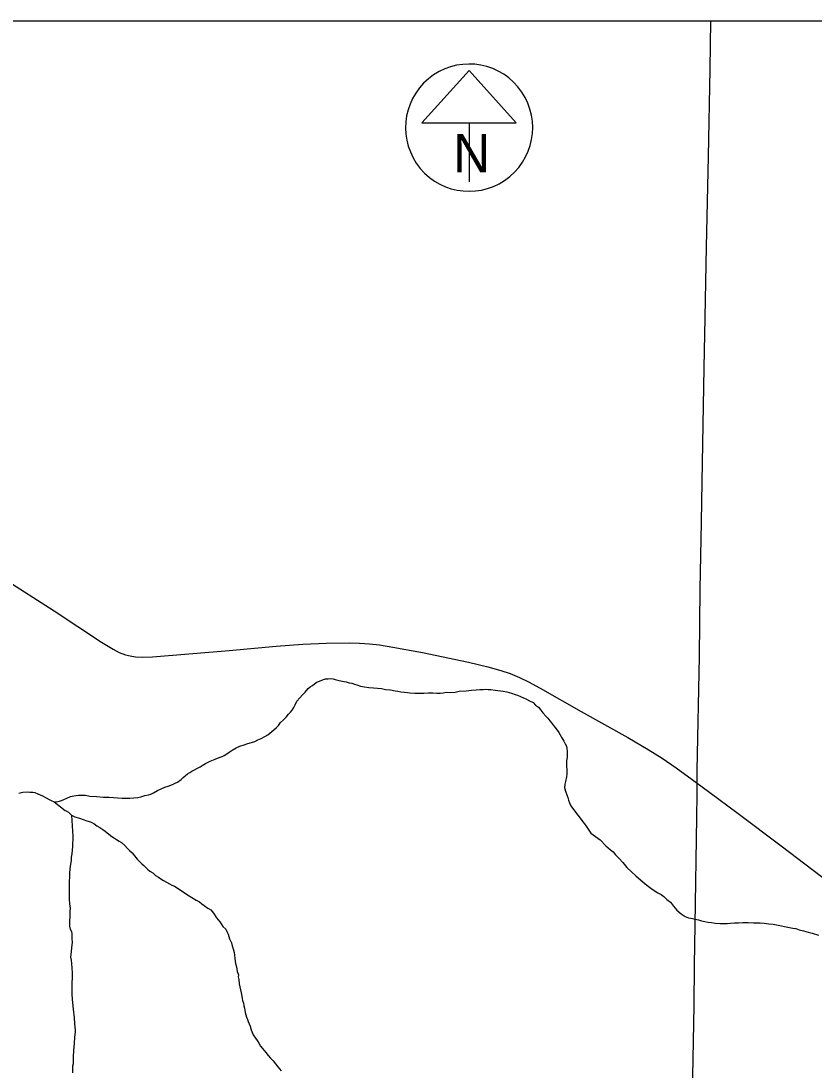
# Model space of a CAD drawing. Extents: x 1 to 1675, y -2 to 1113.
# Drawn here: x 1661.53 to 1666.71, y 1098.56 to 1105.4 of the extents above; entities that cross this region are included whole.
import ezdxf

# ---------------------------------------------------------------- set-up
doc = ezdxf.new("R2010")
doc.units = 0
for name, color, linetype in [('SC_Scratch1', 7, 'Continuous'), ('SH_Data', 7, 'Continuous'), ('SN_P_Text', 7, 'Continuous')]:
    doc.layers.add(name, color=color, linetype=linetype)

msp = doc.modelspace()

# ---------------------------------------------------------------- linework, layer by layer
at = {"layer": 'SC_Scratch1'}
for points in [[(1661.7617, 1100.3085), (1661.7832, 1100.3135), (1661.7967, 1100.3161), (1661.8129, 1100.3239), (1661.8318, 1100.3317), (1661.8561, 1100.3421), (1661.8776, 1100.3471), (1661.9072, 1100.3521), (1661.9341, 1100.3518), (1661.9529, 1100.3515), (1661.9823, 1100.3458), (1662.0253, 1100.3425), (1662.0709, 1100.3392), (1662.1058, 1100.3388), (1662.1353, 1100.3357), (1662.1648, 1100.3353), (1662.1916, 1100.3323), (1662.2185, 1100.332), (1662.2427, 1100.3316), (1662.2669, 1100.334), (1662.2937, 1100.3363), (1662.3153, 1100.3414), (1662.3396, 1100.3491), (1662.3638, 1100.3542), (1662.38, 1100.3593), (1662.3962, 1100.3671), (1662.4232, 1100.3828), (1662.4475, 1100.3932), (1662.4719, 1100.4036), (1662.4934, 1100.4114), (1662.5204, 1100.4217), (1662.5393, 1100.4295), (1662.5528, 1100.4374), (1662.5772, 1100.4531), (1662.5908, 1100.4664), (1662.6044, 1100.4769), (1662.6179, 1100.4901), (1662.6342, 1100.5006), (1662.6477, 1100.5085), (1662.7018, 1100.5372), (1662.7153, 1100.5451), (1662.737, 1100.5582), (1662.7667, 1100.5739), (1662.7991, 1100.5869), (1662.8261, 1100.5972), (1662.845, 1100.605), (1662.8585, 1100.6102), (1662.8747, 1100.6207), (1662.891, 1100.6312), (1662.9099, 1100.6443), (1662.937, 1100.6601), (1662.9613, 1100.6704), (1662.9883, 1100.6808), (1663.0125, 1100.6885), (1663.0368, 1100.6962), (1663.0584, 1100.7013), (1663.0773, 1100.7118), (1663.0989, 1100.7222), (1663.1232, 1100.7353), (1663.1422, 1100.7458), (1663.1557, 1100.7563), (1663.1829, 1100.7774), (1663.1992, 1100.7932), (1663.2128, 1100.8064), (1663.2264, 1100.825), (1663.2455, 1100.8435), (1663.2618, 1100.8594), (1663.2781, 1100.8806), (1663.2917, 1100.8938), (1663.3026, 1100.9071), (1663.3136, 1100.923), (1663.3219, 1100.9416), (1663.3329, 1100.9656), (1663.352, 1100.9868), (1663.3683, 1101.0053), (1663.3874, 1101.0238), (1663.4065, 1101.0477), (1663.42, 1101.0582), (1663.4336, 1101.0661), (1663.458, 1101.0872), (1663.5066, 1101.1053), (1663.5201, 1101.1105), (1663.5362, 1101.1103), (1663.5523, 1101.1127), (1663.5684, 1101.1098), (1663.5818, 1101.107), (1663.6005, 1101.1014), (1663.6273, 1101.0957), (1663.6541, 1101.0899), (1663.6728, 1101.0843), (1663.6916, 1101.0814), (1663.7076, 1101.0759), (1663.7237, 1101.0703), (1663.7477, 1101.0619), (1663.7745, 1101.0589), (1663.8013, 1101.0532), (1663.8335, 1101.0528), (1663.8577, 1101.0498), (1663.8845, 1101.0468), (1663.9113, 1101.041), (1663.9435, 1101.0379)], [(1663.9435, 1101.0379), (1663.9729, 1101.0322), (1663.9917, 1101.0293), (1664.0105, 1101.0263), (1664.0346, 1101.0233), (1664.0533, 1101.0204), (1664.0695, 1101.0202), (1664.1017, 1101.0171), (1664.1339, 1101.0167), (1664.1607, 1101.0163), (1664.1903, 1101.0186), (1664.2198, 1101.0182), (1664.2467, 1101.0179), (1664.2682, 1101.0176), (1664.287, 1101.0201), (1664.3058, 1101.0225), (1664.3354, 1101.0221), (1664.3649, 1101.0244), (1664.3918, 1101.0294), (1664.4375, 1101.0315), (1664.4725, 1101.0364), (1664.5021, 1101.0387), (1664.5263, 1101.041), (1664.5477, 1101.0407), (1664.5639, 1101.0432), (1664.58, 1101.0403), (1664.5988, 1101.0401), (1664.6256, 1101.037), (1664.6792, 1101.031), (1664.7033, 1101.0253), (1664.7328, 1101.0169), (1664.7568, 1101.0085), (1664.7729, 1101.003), (1664.7916, 1100.9947), (1664.8103, 1100.9864), (1664.8316, 1100.9781), (1664.8503, 1100.9671), (1664.8743, 1100.9561), (1664.8902, 1100.9398), (1664.9089, 1100.9262), (1664.9247, 1100.9072), (1664.9379, 1100.8883), (1664.9565, 1100.8666), (1664.9697, 1100.853), (1664.9829, 1100.8368), (1664.9935, 1100.8233), (1665.0067, 1100.807), (1665.0253, 1100.7854), (1665.0411, 1100.761), (1665.0621, 1100.7259), (1665.0753, 1100.7043), (1665.0831, 1100.6855), (1665.091, 1100.672), (1665.0935, 1100.6559), (1665.0959, 1100.6398), (1665.0957, 1100.6237), (1665.0955, 1100.6023), (1665.0924, 1100.5729), (1665.092, 1100.5407), (1665.0944, 1100.5166), (1665.0941, 1100.4898), (1665.0911, 1100.4711), (1665.0854, 1100.4417), (1665.0798, 1100.423), (1665.0795, 1100.3989), (1665.0872, 1100.372), (1665.095, 1100.3532), (1665.1002, 1100.337), (1665.1053, 1100.3182), (1665.1105, 1100.3021), (1665.121, 1100.2832), (1665.1579, 1100.2318), (1665.1738, 1100.2102), (1665.1923, 1100.1858), (1665.2161, 1100.156), (1665.2503, 1100.1047), (1665.3115, 1100.061), (1665.3486, 1100.0204), (1665.3779, 1099.9959), (1665.3965, 1099.9822), (1665.4124, 1099.9633), (1665.4362, 1099.9389), (1665.4601, 1099.9118), (1665.4865, 1099.8793), (1665.5157, 1099.8521), (1665.5449, 1099.8249), (1665.5768, 1099.7977), (1665.6167, 1099.7651), (1665.6512, 1099.7378), (1665.6885, 1099.7159), (1665.7099, 1099.7049), (1665.7258, 1099.6913), (1665.7471, 1099.6723), (1665.771, 1099.6532), (1665.7895, 1099.6289), (1665.8107, 1099.6018), (1665.8399, 1099.5773), (1665.8665, 1099.5609), (1665.8879, 1099.5526), (1665.9147, 1099.5469), (1665.9308, 1099.544)], [(1661.518, 1100.3652), (1661.5449, 1100.3703), (1661.5718, 1100.3726), (1661.5906, 1100.3723), (1661.6094, 1100.3721), (1661.6228, 1100.3692), (1661.6415, 1100.3609), (1661.6735, 1100.3471), (1661.6975, 1100.3334), (1661.7162, 1100.3225), (1661.7295, 1100.3169), (1661.7482, 1100.3087), (1661.7617, 1100.3085)], [(1661.7482, 1100.3087), (1661.82, 1100.2515), (1661.828, 1100.2487), (1661.8414, 1100.2405), (1661.8626, 1100.2214), (1661.8839, 1100.2104), (1661.9134, 1100.202), (1661.9375, 1100.1937), (1661.9615, 1100.1853), (1661.9856, 1100.177), (1662.0069, 1100.166), (1662.0282, 1100.1523), (1662.0469, 1100.1413), (1662.0655, 1100.1277), (1662.0815, 1100.1168), (1662.1054, 1100.0977), (1662.124, 1100.0814), (1662.1427, 1100.0704), (1662.156, 1100.0622), (1662.172, 1100.0513), (1662.188, 1100.0431), (1662.2092, 1100.024), (1662.2278, 1100.005), (1662.2411, 1099.9915), (1662.257, 1099.9752), (1662.2728, 1099.9562), (1662.2914, 1099.9346), (1662.3046, 1099.9183), (1662.3205, 1099.9047), (1662.3338, 1099.8938), (1662.3577, 1099.8694), (1662.3736, 1099.8558), (1662.3923, 1099.8448), (1662.4109, 1099.8285), (1662.4295, 1099.8176), (1662.4455, 1099.8066), (1662.4615, 1099.7957), (1662.4828, 1099.7847), (1662.5015, 1099.7738), (1662.5175, 1099.7655), (1662.5335, 1099.7573), (1662.5895, 1099.7217), (1662.6188, 1099.7026), (1662.6481, 1099.6834), (1662.6747, 1099.667), (1662.6961, 1099.656), (1662.712, 1099.6424), (1662.728, 1099.6315), (1662.7519, 1099.6151), (1662.7706, 1099.6041), (1662.7891, 1099.5825), (1662.8076, 1099.5528), (1662.8181, 1099.5392), (1662.8287, 1099.5257), (1662.8393, 1099.5122), (1662.8498, 1099.496), (1662.8684, 1099.477), (1662.8763, 1099.4635), (1662.8841, 1099.4446), (1662.8893, 1099.4311), (1662.8918, 1099.4151), (1662.8997, 1099.4016), (1662.9049, 1099.3881), (1662.91, 1099.3693), (1662.9178, 1099.3504), (1662.9229, 1099.3263), (1662.9253, 1099.3075), (1662.9277, 1099.286), (1662.9327, 1099.2538), (1662.9378, 1099.2323), (1662.9403, 1099.2162), (1662.9428, 1099.2028), (1662.9506, 1099.1812), (1662.9504, 1099.1679), (1662.9529, 1099.1491), (1662.9552, 1099.1222), (1662.9679, 1099.0632), (1662.973, 1099.0417), (1662.9755, 1099.0255), (1662.978, 1099.0121), (1662.9832, 1098.996), (1662.9856, 1098.9772), (1662.9908, 1098.9637), (1662.9933, 1098.9503), (1662.9958, 1098.9342), (1663.0035, 1098.9047), (1663.0113, 1098.8885), (1663.0139, 1098.875), (1663.0269, 1098.8454), (1663.0347, 1098.8212), (1663.0477, 1098.7889), (1663.0635, 1098.7672), (1663.0741, 1098.751), (1663.0846, 1098.7348), (1663.0951, 1098.7159), (1663.1083, 1098.6997), (1663.1295, 1098.6726), (1663.1454, 1098.6537), (1663.1613, 1098.6374), (1663.1771, 1098.6184), (1663.193, 1098.5995)], [(1661.8626, 1100.2214), (1661.8716, 1100.082), (1661.8681, 1100.0178), (1661.8648, 1099.9696), (1661.8592, 1099.9483), (1661.8589, 1099.9268), (1661.8531, 1099.8894), (1661.8498, 1099.8466), (1661.8461, 1099.7609), (1661.8456, 1099.7234), (1661.8477, 1099.6752), (1661.8499, 1099.6403), (1661.8523, 1099.6162), (1661.852, 1099.5921), (1661.8516, 1099.5626), (1661.8485, 1099.5305), (1661.8483, 1099.5118), (1661.8481, 1099.4984), (1661.8532, 1099.4769), (1661.8611, 1099.4634), (1661.8636, 1099.4473), (1661.8634, 1099.4312), (1661.8632, 1099.4178), (1661.8656, 1099.391), (1661.8625, 1099.3589), (1661.8594, 1099.3295), (1661.8563, 1099.2947), (1661.8588, 1099.2759), (1661.8612, 1099.2545), (1661.8658, 1099.1928), (1661.8645, 1099.0964), (1661.8641, 1099.0562), (1661.8663, 1099.0187), (1661.8735, 1098.9569), (1661.8782, 1098.9006), (1661.8804, 1098.8631), (1661.8828, 1098.839), (1661.8852, 1098.8202), (1661.8851, 1098.8068), (1661.882, 1098.7747), (1661.8788, 1098.7319), (1661.8755, 1098.6864), (1661.8723, 1098.6463), (1661.872, 1098.6195), (1661.8717, 1098.6007), (1661.8689, 1098.5847), (1661.8687, 1098.5713), (1661.8683, 1098.5418)], [(1665.9308, 1099.544), (1665.9522, 1099.5383), (1665.9736, 1099.5327), (1665.995, 1099.527), (1666.0138, 1099.5241), (1666.0379, 1099.5211), (1666.062, 1099.5181), (1666.0942, 1099.515), (1666.1211, 1099.5147), (1666.1399, 1099.5144), (1666.1614, 1099.5168), (1666.1883, 1099.5192), (1666.2151, 1099.5188), (1666.242, 1099.5211), (1666.2769, 1099.5207), (1666.3118, 1099.5202), (1666.3333, 1099.5199), (1666.3548, 1099.5197), (1666.3816, 1099.5166), (1666.4111, 1099.5136), (1666.4406, 1099.5105), (1666.5692, 1099.4847), (1666.5879, 1099.4818), (1666.6093, 1099.4735), (1666.6388, 1099.4677), (1666.6682, 1099.4593), (1666.695, 1099.4509), (1666.7351, 1099.4397)], [(1663.193, 1098.5995), (1663.2089, 1098.5805), (1663.23, 1098.5535)]]:
    msp.add_lwpolyline(points, dxfattribs=at)
at = {"layer": 'SH_Data'}
for p, q in [((1664.4562, 1105.0786), (1664.1486, 1104.7374)), ((1664.7637, 1104.7374), (1664.4562, 1105.0786)), ((1664.1486, 1104.7374), (1664.7637, 1104.7374)), ((1664.4562, 1104.7374), (1664.4562, 1104.3506))]:
    msp.add_line(p, q, dxfattribs=at)
msp.add_lwpolyline([(1653.1763, 1105.4005), (1672.2022, 1105.4005), (1672.2022, 1085.8005), (1653.1763, 1085.8005)], close=True, dxfattribs=at)
msp.add_arc((1664.4562, 1104.7049), 0.4148, 129.77984, 129.76332, dxfattribs=at)
at = {"layer": 'SN_P_Text'}
for points in [[(1665.9448, 1100.4293), (1665.945, 1100.5124), (1665.9606, 1101.2565), (1665.9647, 1101.6943), (1665.9735, 1102.132), (1665.9767, 1102.3948), (1665.9902, 1103.1389), (1665.9974, 1103.4671), (1666.0058, 1103.9268), (1666.0181, 1104.5177), (1666.0282, 1105.0868), (1666.0339, 1105.4005)], [(1665.9448, 1100.4293), (1665.945, 1100.5124), (1665.9606, 1101.2565), (1665.9647, 1101.6943), (1665.9735, 1102.132), (1665.9767, 1102.3948), (1665.9902, 1103.1389), (1665.9974, 1103.4671), (1666.0058, 1103.9268), (1666.0181, 1104.5177), (1666.0282, 1105.0868), (1666.0339, 1105.4005)], [(1661.4164, 1101.767), (1661.7478, 1101.5543), (1662.0586, 1101.3498), (1662.1332, 1101.303), (1662.1727, 1101.2827), (1662.2141, 1101.2666), (1662.2443, 1101.2594), (1662.2791, 1101.2538), (1662.3234, 1101.2514), (1662.3896, 1101.2541), (1662.8915, 1101.2959), (1663.1966, 1101.3229), (1663.3709, 1101.3362), (1663.5238, 1101.3426), (1663.6767, 1101.3449), (1663.742, 1101.3432), (1663.8071, 1101.3386), (1663.8721, 1101.3312), (1663.9583, 1101.3175), (1664.1517, 1101.2814), (1664.4517, 1101.22), (1664.5792, 1101.1894), (1664.6631, 1101.1657), (1664.7248, 1101.1448), (1664.785, 1101.1198), (1664.8438, 1101.0913), (1664.9206, 1101.0498), (1665.1868, 1100.8983), (1665.4927, 1100.7281), (1665.6245, 1100.6505), (1665.7167, 1100.5921), (1665.8066, 1100.5302), (1665.9127, 1100.4531), (1665.9448, 1100.4293)], [(1661.4164, 1101.767), (1661.7478, 1101.5543), (1662.0586, 1101.3498), (1662.1332, 1101.303), (1662.1727, 1101.2827), (1662.2141, 1101.2666), (1662.2443, 1101.2594), (1662.2791, 1101.2538), (1662.3234, 1101.2514), (1662.3896, 1101.2541), (1662.8915, 1101.2959), (1663.1966, 1101.3229), (1663.3709, 1101.3362), (1663.5238, 1101.3426), (1663.6767, 1101.3449), (1663.742, 1101.3432), (1663.8071, 1101.3386), (1663.8721, 1101.3312), (1663.9583, 1101.3175), (1664.1517, 1101.2814), (1664.4517, 1101.22), (1664.5792, 1101.1894), (1664.6631, 1101.1657), (1664.7248, 1101.1448), (1664.785, 1101.1198), (1664.8438, 1101.0913), (1664.9206, 1101.0498), (1665.1868, 1100.8983), (1665.4927, 1100.7281), (1665.6245, 1100.6505), (1665.7167, 1100.5921), (1665.8066, 1100.5302), (1665.9127, 1100.4531), (1665.9448, 1100.4293)], [(1665.8647, 1095.6018), (1665.8652, 1095.6384), (1665.8691, 1095.9598), (1665.8824, 1096.7478), (1665.891, 1097.2512), (1665.9023, 1097.8203), (1665.9237, 1098.9803), (1665.9265, 1099.243), (1665.9316, 1099.5056), (1665.9414, 1100.206), (1665.9454, 1100.3592), (1665.9448, 1100.4293)], [(1665.8647, 1095.6018), (1665.8652, 1095.6384), (1665.8691, 1095.9598), (1665.8824, 1096.7478), (1665.891, 1097.2512), (1665.9023, 1097.8203), (1665.9237, 1098.9803), (1665.9265, 1099.243), (1665.9316, 1099.5056), (1665.9414, 1100.206), (1665.9454, 1100.3592), (1665.9448, 1100.4293)], [(1665.9448, 1100.4293), (1666.0184, 1100.3751), (1666.2125, 1100.233), (1666.4914, 1100.0215), (1666.7014, 1099.8638), (1666.9271, 1099.6908), (1667.1733, 1099.5083), (1667.4005, 1099.3373), (1667.5592, 1099.2201), (1667.5964, 1099.1962), (1667.6357, 1099.1755), (1667.6562, 1099.1669), (1667.6773, 1099.1594), (1667.6988, 1099.1537), (1667.7205, 1099.1492), (1667.7425, 1099.1461), (1667.8086, 1099.1416), (1667.8763, 1099.1402)], [(1665.9448, 1100.4293), (1666.0184, 1100.3751), (1666.2125, 1100.233), (1666.4914, 1100.0215), (1666.7014, 1099.8638), (1666.9271, 1099.6908)]]:
    msp.add_lwpolyline(points, dxfattribs=at)

# ---------------------------------------------------------------- texts
at = {"layer": 'SH_Data'}
msp.add_text('N', height=0.25, dxfattribs=at).set_placement((1664.3521, 1104.4135))

doc.saveas('drawing.dxf')
